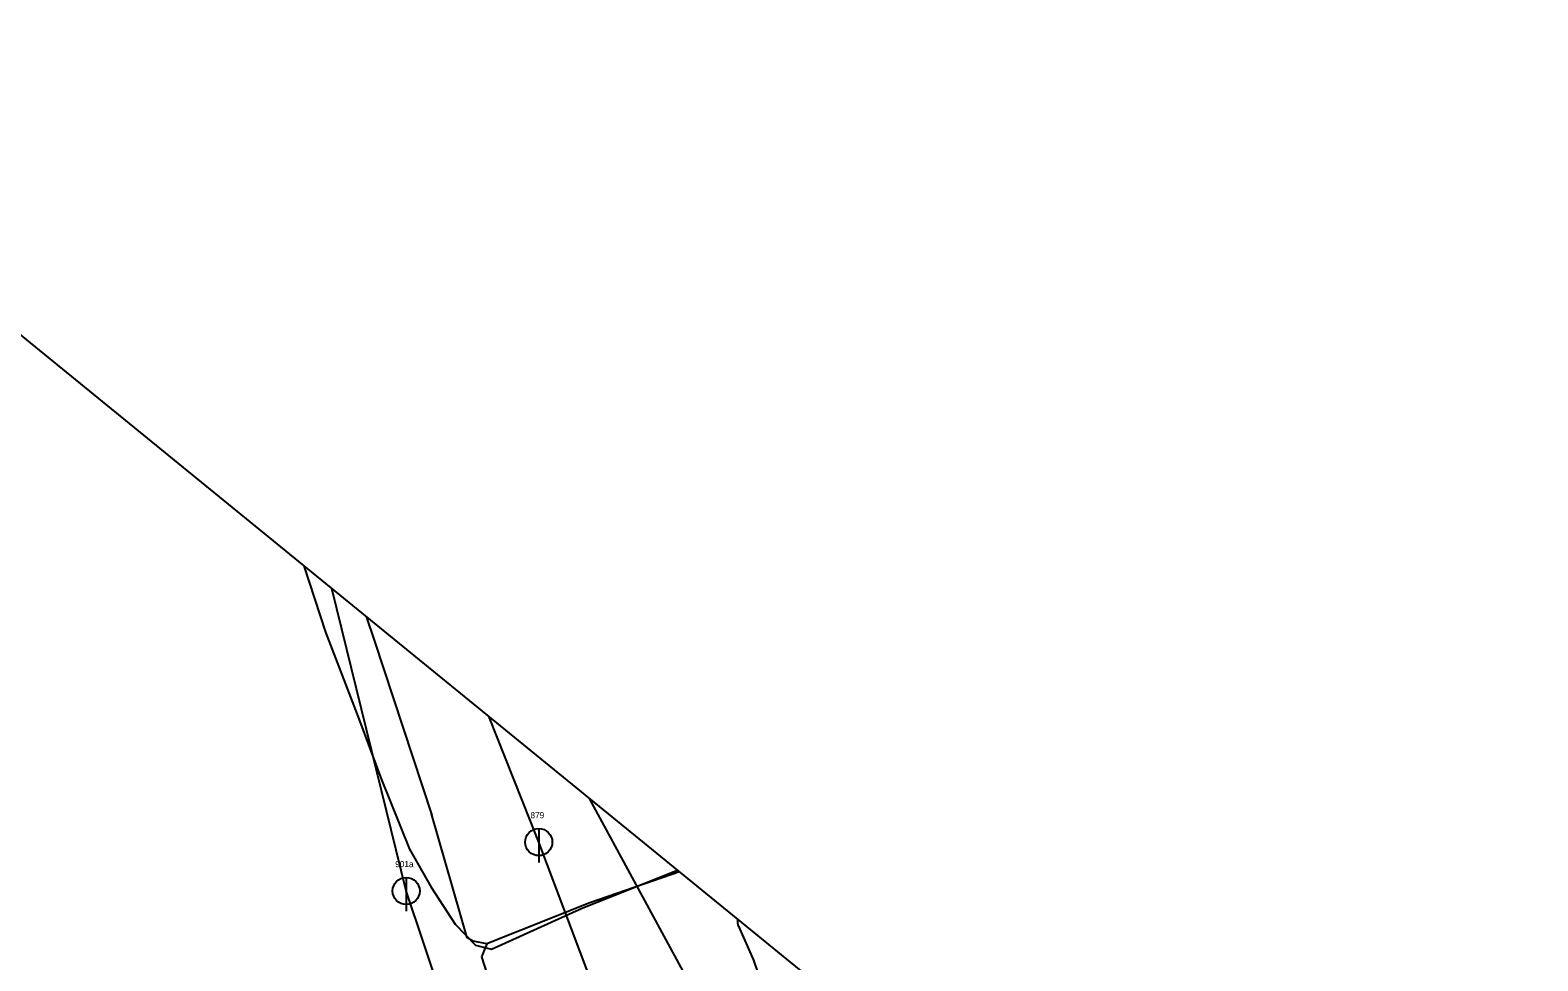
# Model space of a CAD drawing. Extents: x -492431 to -49223, y -1127123 to -112687.
# Drawn here: x -492244.4 to -492133, y -1126931.2 to -1126862.5 of the extents above; entities that cross this region are included whole.
import ezdxf

# ---------------------------------------------------------------- set-up
doc = ezdxf.new("R2010")
doc.units = 0
for name, color, linetype in [('Vrstva 1', 7, 'Continuous'), ('Vrstva 15', 7, 'Continuous'), ('Vrstva 17', 7, 'Continuous'), ('Vrstva 19', 7, 'Continuous'), ('Vrstva 26', 7, 'Continuous'), ('Vrstva 5', 7, 'Continuous')]:
    doc.layers.add(name, color=color, linetype=linetype)

msp = doc.modelspace()

# ---------------------------------------------------------------- linework, layer by layer
at = {"layer": 'Vrstva 1'}
msp.add_lwpolyline([(-492341.24, -1127122.91), (-492133.03, -1126976.26), (-492272.7, -1126862.46), (-492313.78, -1126867.2)], dxfattribs=at)
at = {"layer": 'Vrstva 15'}
for p, q in [((-492216.6, -1126926.03), (-492222.08, -1126903.7)), ((-492206.81, -1126922.42), (-492210.5, -1126913.13)), ((-492182.01, -1126957.94), (-492203.06, -1126919.2)), ((-492194.04, -1126956.14), (-492206.81, -1126922.42)), ((-492203.42, -1126965.32), (-492216.6, -1126926.03))]:
    msp.add_line(p, q, dxfattribs=at)
at = {"layer": 'Vrstva 17'}
for p, q in [((-492206.81, -1126921.42), (-492206.81, -1126923.92)), ((-492216.6, -1126925.03), (-492216.6, -1126927.53))]:
    msp.add_line(p, q, dxfattribs=at)
for centre in [(-492206.81, -1126922.42), (-492216.6, -1126926.03)]:
    msp.add_circle(centre, 1, dxfattribs=at)
at = {"layer": 'Vrstva 26'}
for p, q in [((-492219.56, -1126905.75), (-492218.97, -1126907.5)), ((-492218.97, -1126907.5), (-492214.7, -1126920.42)), ((-492212.09, -1126929.5), (-492214.73, -1126920.34)), ((-492196.42, -1126924.61), (-492203.04, -1126926.9)), ((-492203.04, -1126926.9), (-492210.65, -1126929.93)), ((-492192.07, -1126928.62), (-492190.95, -1126931.14)), ((-492211.65, -1126929.74), (-492212.09, -1126929.5)), ((-492210.65, -1126929.93), (-492211.65, -1126929.74)), ((-492210.65, -1126929.93), (-492211.04, -1126930.89)), ((-492211.04, -1126930.89), (-492210.42, -1126932.81)), ((-492190.95, -1126931.14), (-492186.68, -1126943.68))]:
    msp.add_line(p, q, dxfattribs=at)
msp.add_arc((-492191.45, -1126928.33), 0.684, 162.1977, 204.7446, dxfattribs=at)
at = {"layer": 'Vrstva 5'}
msp.add_lwpolyline([(-492224.15, -1126902.01), (-492222.56, -1126906.91), (-492220.09, -1126913.31), (-492218.45, -1126917.75), (-492216.36, -1126922.94), (-492214.76, -1126925.74), (-492212.97, -1126928.47), (-492211.47, -1126930.02), (-492210.31, -1126930.32), (-492203.56, -1126927.28), (-492196.57, -1126924.48)], dxfattribs=at)

# ---------------------------------------------------------------- texts
at = {"layer": 'Vrstva 19'}
for s, p in [('879', (-492207.42, -1126920.66)), ('901a', (-492217.41, -1126924.27))]:
    msp.add_text(s, height=0.455, dxfattribs=at).set_placement(p)

doc.saveas('drawing.dxf')
